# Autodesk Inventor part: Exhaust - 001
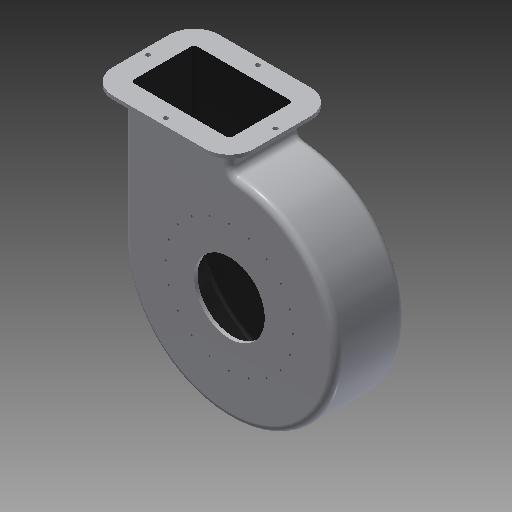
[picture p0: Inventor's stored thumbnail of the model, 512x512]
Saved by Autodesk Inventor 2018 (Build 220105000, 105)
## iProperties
Created: 2006-05
Part Number: Exhaust - 001
Document SubType Name: Modeling
Designer: Autodesk, Inc.
Density: 2.71 g/cm^3
Material: Aluminum-6061
Mass: 27045.4 g
Surface Area: 19920.1 cm^2
Volume: 9979.84 cm^3
Appearance: Aluminum - Flat
Author: Autodesk, Inc.
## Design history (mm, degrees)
derived "MainGeom.ipt"
sketch "Sketch1" dims "d42" = 600
  geometry: L1 (0, 370)-(-300, 370); L2 (-300, 0)-(-300, 370); L3 (-200, 0)-(-200, -350); L4 (-200, -350)-(200, -350); L5 (200, -350)-(200, 0); L6 (0, 370)-(0, 300); C1 r 100 at (0, 0); C2 r 25 at (0, 0); A1 r 200 centre (0, 0) between (200, 0) and (-200, 0); 2 further points
  constraints: 12 end point, 3 centre point, 3 vertical, 2 horizontal, 2 point on circle, 2 point on line, 1 coincident, 5 other
  dimensions: "d41" = 50 diameter of C2; "d43" = 200 radius of A1; "d44" = 200 diameter of C1; "d45" = 350 distance from line of L4 point (0, 0); "d46" = 370 distance from line of L1 point (0, 0)
extrude "Extrusion1" new body sketch "Sketch1" distance "d1" = 200; taper "d2" = 0 deg
fillet "Fillet1" dims "d37" = 20
sketch "Sketch12"
  geometry: L1 (-20, -20)-(-20, -180) reference; L2 (0, -200)-(260, -200) reference; L3 (280, -20)-(280, -180) reference; L4 (260, 0)-(0, 0) reference; L5 (-70, -20)-(-70, -180); L6 (0, -250)-(260, -250); L7 (330, -180)-(330, -20); L8 (260, 50)-(0, 50); L9 (-50, -20)-(-50, -180); L10 (0, -230)-(260, -230); L11 (310, -180)-(310, -20); L12 (260, 30)-(0, 30); C1 r 6.35 at (130, 30); C2 r 6.35 at (-50, -100); C3 r 6.35 at (130, -230); C4 r 6.35 at (310, -100); A1 r 20 centre (0, -20) between (0, 0) and (-20, -20) reference; A2 r 20 centre (0, -180) between (-20, -180) and (0, -200) reference; A3 r 20 centre (260, -180) between (260, -200) and (280, -180) reference; A4 r 20 centre (260, -20) between (280, -20) and (260, 0) reference; A5 r 70 centre (0, -20) between (0, 50) and (-70, -20); A6 r 70 centre (0, -180) between (-70, -180) and (0, -250); A7 r 70 centre (260, -180) between (260, -250) and (330, -180); A8 r 70 centre (260, -20) between (330, -20) and (260, 50); A9 r 50 centre (0, -20) between (0, 30) and (-50, -20); A10 r 50 centre (0, -180) between (-50, -180) and (0, -230); A11 r 50 centre (260, -180) between (260, -230) and (310, -180); A12 r 50 centre (260, -20) between (310, -20) and (260, 30); 5 further points
  constraints: 16 end point, 16 point on circle, 12 centre point, 4 coincident, 4 midpoint, 3 equal radius, 14 other
  dimensions: "d54" = 50 distance between parallel lines of L8 L4; "d55" = 30 distance between parallel lines of L4 L12; "d58" = 400 distance between parallel lines of L7 L5 (derived); "d59" = 300 distance between parallel lines of L6 L8 (derived); "d60" = 12.7 diameter of C3
  node "Projected Loop2"
extrude "Extrusion8" join sketch "Sketch12" distance "d47" = 10.16 (= Thickness); taper "d48" = 0 deg
shell "Shell1" dims "d17" = 10.16 (= Thickness)
extrude "Extrusion4" cut sketch "Sketch1" stored distance "d18" = 100; taper "d19" = 0 deg
extrude "Extrusion9" cut sketch "Sketch1" extent not by distance; stored distance "d49" = 10.16 (= Thickness); taper "d50" = 0 deg
sketch "Sketch8" dims "d26" = 360
  geometry: 3 further points
  constraints: 2 vertical alignment, 1 coincident, 2 other
hole "Hole1" sketch "Sketch8" at (280, -190) diameter "d27" = 7.7978; stored, may be unused: countersink angle "d31" = 90 deg, drill point angle "d33" = 118 deg; dims "d28" = 6, "d29" = 4, "d30" = 2, "d32" = 8
extrude "Extrusion10" cut sketch "Sketch12" extent not by distance; stored distance "d56" = 10.16 (= Thickness); taper "d57" = 0 deg
body "Solid1"
pattern_circular "Circular Pattern2" dims angle "d52" = 360 deg
other parameters: "Thickness" = 10.16 [user parameter; used in 4 equation terms]
